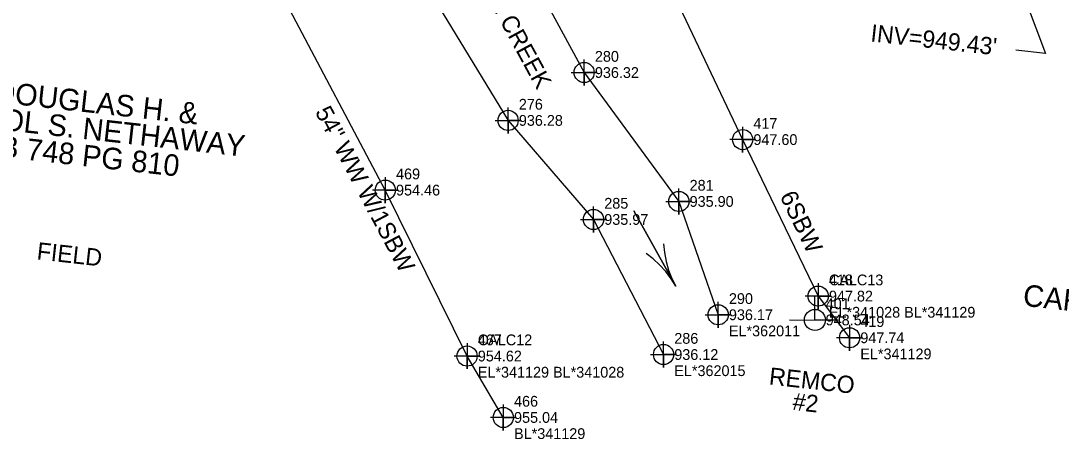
# Model space of a CAD drawing. Extents: x 1150279 to 1151282, y 654632 to 657999.
# Drawn here: x 1150667.5 to 1150909.2, y 656974.2 to 657071.3 of the extents above; entities that cross this region are included whole.
import ezdxf

# ---------------------------------------------------------------- set-up
doc = ezdxf.new("R2010")
doc.units = 0
for name, color, linetype in [('Exist Hydro Jurisdictional Stream or Body of Water', 7, 'Continuous'), ('Exist Hydro Jurisdictional Stream or Body of Water Text', 7, 'Continuous'), ('Exist Hydro River Flow Arrow CELL', 7, 'Continuous'), ('Exist Hydro Stream or Body of Water Cogo Comment', 7, 'Continuous'), ('Exist Hydro Stream or Body of Water Cogo Elevation', 7, 'Continuous'), ('Exist Hydro Stream or Body of Water Cogo Number', 7, 'Continuous'), ('Exist Hydro Stream or Body of Water Cogo Point CELL', 7, 'Continuous'), ('Exist Other Culture Fence Line', 7, 'Continuous'), ('Exist Other Culture Fence Line Cogo Comment', 7, 'Continuous'), ('Exist Other Culture Fence Line Cogo Elevation', 7, 'Continuous'), ('Exist Other Culture Fence Line Cogo Number', 7, 'Continuous'), ('Exist Other Culture Fence Line Cogo Point CELL', 7, 'Continuous'), ('Exist Other Culture Fence Line Text', 7, 'Continuous'), ('Exist Other Culture Gate', 7, 'Continuous'), ('Exist Other Culture Gate Cogo Comment', 7, 'Continuous'), ('Exist Other Culture Gate Cogo Elevation', 7, 'Continuous'), ('Exist Other Culture Gate Cogo Number', 7, 'Continuous'), ('Exist Other Culture Gate Cogo Point CELL', 7, 'Continuous'), ('Exist Property Deed Book Text', 7, 'Continuous'), ('Exist Property Owner Text', 7, 'Continuous'), ('Exist Structure Minor Pipes CMP 15 Inch Leader', 7, 'Continuous'), ('Exist Structure Minor Pipes CMP 15 Inch Text', 7, 'Continuous'), ('Exist Utilities Power Joint Use Telephone CELL', 7, 'Continuous'), ('Exist Utilities Power Joint Use Telephone Cogo Elevation', 7, 'Continuous'), ('Exist Utilities Power Joint Use Telephone Cogo Number', 7, 'Continuous'), ('Exist Utilities Power Joint Use Telephone Text', 7, 'Continuous'), ('Exist Vegetation Woods Line Text', 7, 'Continuous')]:
    doc.layers.add(name, color=color, linetype=linetype)

msp = doc.modelspace()

# ---------------------------------------------------------------- linework, layer by layer
at = {"layer": 'Exist Hydro Jurisdictional Stream or Body of Water'}
for points in [[(1150745.79, 657124.78), (1150745.93, 657121.28), (1150758.49, 657084.64), (1150780.67, 657048.19), (1150800.52, 657025.21), (1150816.79, 656993.87)], [(1150769.35, 657125.31), (1150769.52, 657122.14), (1150780.79, 657091.68), (1150798.34, 657059.3), (1150820.35, 657029.39), (1150829.48, 657003.1)]]:
    msp.add_lwpolyline(points, dxfattribs=at)
at = {"layer": 'Exist Hydro River Flow Arrow CELL'}
msp.add_line((1150814.76, 657018.44), (1150814.76, 657018.44), dxfattribs=at)
msp.add_lwpolyline([(1150816.76, 657019.55), (1150816.99, 657017.52), (1150817.39, 657015.49), (1150817.96, 657013.47), (1150818.69, 657011.53), (1150819.62, 657009.7), (1150809.9, 657027.18), (1150819.62, 657009.7), (1150818.56, 657011.46), (1150817.29, 657013.1), (1150815.88, 657014.65), (1150814.37, 657016.06), (1150812.76, 657017.33)], dxfattribs=at)
at = {"layer": 'Exist Hydro Stream or Body of Water Cogo Point CELL'}
for points in [[(1150795.34, 657059.3), (1150801.34, 657059.3), (1150798.34, 657059.3), (1150798.34, 657056.3), (1150798.34, 657062.3)], [(1150777.67, 657048.19), (1150783.67, 657048.19), (1150780.67, 657048.19), (1150780.67, 657045.19), (1150780.67, 657051.19)], [(1150817.35, 657029.39), (1150823.35, 657029.39), (1150820.35, 657029.39), (1150820.35, 657026.39), (1150820.35, 657032.39)], [(1150797.52, 657025.21), (1150803.52, 657025.21), (1150800.52, 657025.21), (1150800.52, 657022.21), (1150800.52, 657028.21)], [(1150826.48, 657003.1), (1150832.48, 657003.1), (1150829.48, 657003.1), (1150829.48, 657000.1), (1150829.48, 657006.1)], [(1150813.79, 656993.87), (1150819.79, 656993.87), (1150816.79, 656993.87), (1150816.79, 656990.87), (1150816.79, 656996.87)]]:
    msp.add_lwpolyline(points, dxfattribs=at)
for centre in [(1150798.34, 657059.3), (1150780.67, 657048.19), (1150820.35, 657029.39), (1150800.52, 657025.21), (1150829.48, 657003.1), (1150816.79, 656993.87)]:
    msp.add_circle(centre, 2.34, dxfattribs=at)
at = {"layer": 'Exist Other Culture Fence Line'}
for points in [[(1151064.38, 657042.2), (1151035.79, 657039.66), (1150986.53, 657050.15), (1150941.42, 657063.2), (1150898.39, 657078.65), (1150854.86, 657094.99), (1150825.03, 657100.53), (1150812.46, 657091.59), (1150835.17, 657043.74), (1150852.72, 657007.43)], [(1150771.14, 656993.52), (1150752.14, 657032.02), (1150729.28, 657075.13), (1150719.49, 657093.07), (1150693.83, 657099.27)]]:
    msp.add_lwpolyline(points, dxfattribs=at)
at = {"layer": 'Exist Other Culture Fence Line Cogo Point CELL'}
for points in [[(1150835.17, 657046.74), (1150835.17, 657040.74), (1150835.17, 657043.74), (1150838.17, 657043.74), (1150832.17, 657043.74)], [(1150752.14, 657035.02), (1150752.14, 657029.02), (1150752.14, 657032.02), (1150755.14, 657032.02), (1150749.14, 657032.02)], [(1150852.72, 657010.43), (1150852.72, 657004.43), (1150852.72, 657007.43), (1150855.72, 657007.43), (1150849.72, 657007.43)], [(1150771.14, 656996.52), (1150771.14, 656990.52), (1150771.14, 656993.52), (1150774.14, 656993.52), (1150768.14, 656993.52)]]:
    msp.add_lwpolyline(points, dxfattribs=at)
for centre in [(1150835.17, 657043.74), (1150752.14, 657032.02), (1150852.72, 657007.43), (1150771.14, 656993.52)]:
    msp.add_circle(centre, 2.34, dxfattribs=at)
at = {"layer": 'Exist Other Culture Gate'}
for p, q in [((1150852.72, 657007.43), (1150860.01, 656997.76)), ((1150779.56, 656979.27), (1150771.14, 656993.52))]:
    msp.add_line(p, q, dxfattribs=at)
at = {"layer": 'Exist Other Culture Gate Cogo Point CELL'}
for points in [[(1150852.72, 657010.43), (1150852.72, 657004.43), (1150852.72, 657007.43), (1150855.72, 657007.43), (1150849.72, 657007.43)], [(1150860.01, 657000.76), (1150860.01, 656994.76), (1150860.01, 656997.76), (1150863.01, 656997.76), (1150857.01, 656997.76)], [(1150771.14, 656996.52), (1150771.14, 656990.52), (1150771.14, 656993.52), (1150774.14, 656993.52), (1150768.14, 656993.52)], [(1150779.56, 656982.27), (1150779.56, 656976.27), (1150779.56, 656979.27), (1150782.56, 656979.27), (1150776.56, 656979.27)]]:
    msp.add_lwpolyline(points, dxfattribs=at)
for centre in [(1150852.72, 657007.43), (1150860.01, 656997.76), (1150771.14, 656993.52), (1150779.56, 656979.27)]:
    msp.add_circle(centre, 2.34, dxfattribs=at)
at = {"layer": 'Exist Structure Minor Pipes CMP 15 Inch Leader'}
msp.add_lwpolyline([(1150896.56, 657087.61), (1150905.54, 657063.74), (1150898.67, 657064.5)], dxfattribs=at)
at = {"layer": 'Exist Utilities Power Joint Use Telephone CELL'}
msp.add_line((1150851.96, 657001.89), (1150851.96, 657001.89), dxfattribs=at)
msp.add_lwpolyline([(1150846.02, 657001.89), (1150857.36, 657001.85), (1150851.96, 657001.87), (1150851.96, 657007.52)], dxfattribs=at)
msp.add_circle((1150851.96, 657001.9), 2.45, dxfattribs=at)

# ---------------------------------------------------------------- texts
at = {"layer": 'Exist Hydro Jurisdictional Stream or Body of Water Text'}
msp.add_text('CANE CREEK', height=4, rotation=298.4546, dxfattribs=at).set_placement((1150770.87, 657085.69))
at = {"layer": 'Exist Hydro Stream or Body of Water Cogo Comment'}
for s, p in [('EL*362011', (1150831.98, 656998.1)), ('EL*362015', (1150819.29, 656988.87))]:
    msp.add_text(s, height=2.5, dxfattribs=at).set_placement(p)
at = {"layer": 'Exist Hydro Stream or Body of Water Cogo Elevation'}
for s, p in [('936.32', (1150800.84, 657058.05)), ('936.28', (1150783.17, 657046.94)), ('935.90', (1150822.85, 657028.14)), ('935.97', (1150803.02, 657023.96)), ('936.17', (1150831.98, 657001.85)), ('936.12', (1150819.29, 656992.62))]:
    msp.add_text(s, height=2.5, dxfattribs=at).set_placement(p)
at = {"layer": 'Exist Hydro Stream or Body of Water Cogo Number'}
for s, p in [('280', (1150800.84, 657061.8)), ('276', (1150783.17, 657050.69)), ('281', (1150822.85, 657031.89)), ('285', (1150803.02, 657027.71)), ('290', (1150831.98, 657005.6)), ('286', (1150819.29, 656996.37))]:
    msp.add_text(s, height=2.5, dxfattribs=at).set_placement(p)
at = {"layer": 'Exist Other Culture Fence Line Cogo Comment'}
msp.add_text('EL*341028 BL*341129', height=2.5, dxfattribs=at).set_placement((1150855.22, 657002.43))
at = {"layer": 'Exist Other Culture Fence Line Cogo Elevation'}
for s, p in [('947.60', (1150837.67, 657042.49)), ('954.46', (1150754.64, 657030.77)), ('947.82', (1150855.22, 657006.18)), ('954.62', (1150773.64, 656992.27))]:
    msp.add_text(s, height=2.5, dxfattribs=at).set_placement(p)
at = {"layer": 'Exist Other Culture Fence Line Cogo Number'}
for s, p in [('417', (1150837.67, 657046.24)), ('469', (1150754.64, 657034.52)), ('418', (1150855.22, 657009.93)), ('CALC12', (1150773.64, 656996.02))]:
    msp.add_text(s, height=2.5, dxfattribs=at).set_placement(p)
at = {"layer": 'Exist Other Culture Fence Line Text'}
for s, rotation, p in [('54" WW W/1SBW', 297.9395, (1150735.72, 657050.17)), ('6SBW', 295.7922, (1150843.72, 657030.64))]:
    msp.add_text(s, height=4, rotation=rotation, dxfattribs=at).set_placement(p)
at = {"layer": 'Exist Other Culture Gate Cogo Comment'}
for s, p in [('EL*341129', (1150862.51, 656992.76)), ('EL*341129 BL*341028', (1150773.64, 656988.52)), ('BL*341129', (1150782.06, 656974.27))]:
    msp.add_text(s, height=2.5, dxfattribs=at).set_placement(p)
at = {"layer": 'Exist Other Culture Gate Cogo Elevation'}
for s, p in [('947.82', (1150855.22, 657006.18)), ('947.74', (1150862.51, 656996.51)), ('954.62', (1150773.64, 656992.27)), ('955.04', (1150782.06, 656978.02))]:
    msp.add_text(s, height=2.5, dxfattribs=at).set_placement(p)
at = {"layer": 'Exist Other Culture Gate Cogo Number'}
for s, p in [('CALC13', (1150855.22, 657009.93)), ('419', (1150862.51, 657000.26)), ('467', (1150773.64, 656996.02)), ('466', (1150782.06, 656981.77))]:
    msp.add_text(s, height=2.5, dxfattribs=at).set_placement(p)
at = {"layer": 'Exist Property Deed Book Text'}
msp.add_text('DB 748 PG 810', height=5, rotation=353.6867, dxfattribs=at).set_placement((1150657.48, 657040.3))
at = {"layer": 'Exist Property Owner Text'}
for s, p in [('DOUGLAS H. &', (1150661.13, 657052.47)), ('CAROL S. NETHAWAY', (1150648.74, 657047.56)), ('CAROL S. NETHAWAY', (1150900.13, 657005.21))]:
    msp.add_text(s, height=5, rotation=353.6867, dxfattribs=at).set_placement(p)
at = {"layer": 'Exist Structure Minor Pipes CMP 15 Inch Text'}
msp.add_text("INV=949.43'", height=4, rotation=353.6867, dxfattribs=at).set_placement((1150864.76, 657066.54))
at = {"layer": 'Exist Utilities Power Joint Use Telephone Cogo Elevation'}
msp.add_text('948.54', height=2.5, dxfattribs=at).set_placement((1150854.46, 657000.64))
at = {"layer": 'Exist Utilities Power Joint Use Telephone Cogo Number'}
msp.add_text('401', height=2.5, dxfattribs=at).set_placement((1150854.46, 657004.39))
at = {"layer": 'Exist Utilities Power Joint Use Telephone Text'}
for s, p in [('REMCO', (1150841.17, 656986.94)), ('#2', (1150846.63, 656981.05))]:
    msp.add_text(s, height=4, rotation=353.6867, dxfattribs=at).set_placement(p)
at = {"layer": 'Exist Vegetation Woods Line Text'}
msp.add_text('FIELD', height=4, rotation=353.6867, dxfattribs=at).set_placement((1150671.04, 657015.97))

doc.saveas('drawing.dxf')
